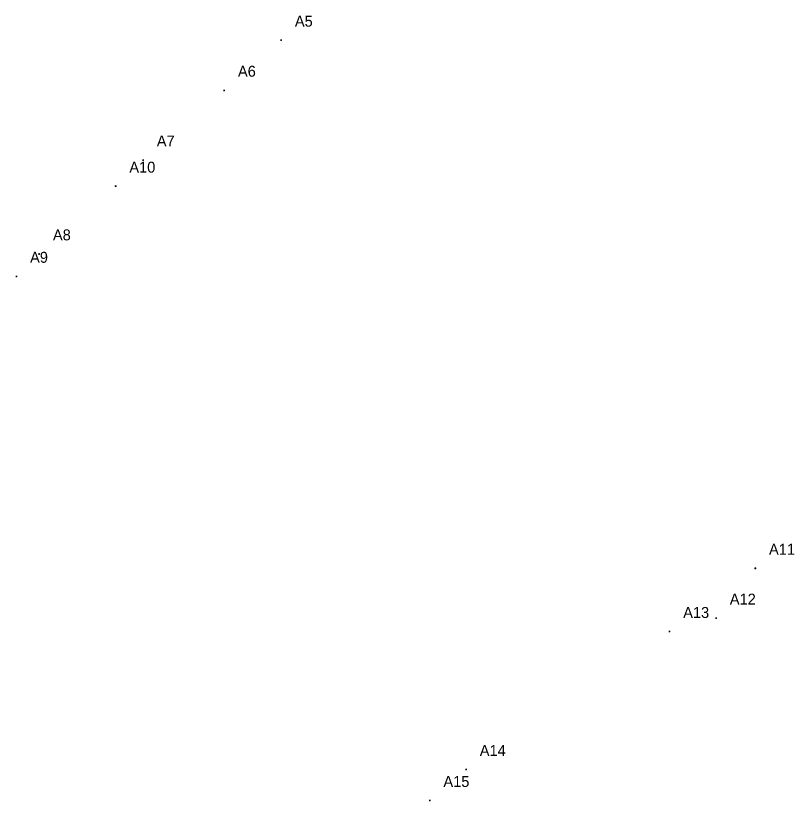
# Model space of a CAD drawing. Extents: x 1727960 to 1749562, y 651707 to 653731.
# Drawn here: x 1731235.4 to 1731520.4, y 651707.4 to 651995.2 of the extents above; entities that cross this region are included whole.
import ezdxf

# ---------------------------------------------------------------- set-up
doc = ezdxf.new("R2010")
doc.units = 0
doc.layers.add('SURVEY - DRAINAGE - Storm Sewer - Points - Locators', color=7, linetype='Continuous')
doc.layers.add('SURVEY - DRAINAGE - Storm Sewer - Points - Numbers', color=7, linetype='Continuous')

msp = doc.modelspace()

# ---------------------------------------------------------------- linework, layer by layer
at = {"layer": 'SURVEY - DRAINAGE - Storm Sewer - Points - Locators'}
for p, q in [((1731332.82, 651986.16), (1731332.32, 651986.16)), ((1731332.57, 651985.91), (1731332.57, 651986.41)), ((1731332.57, 651986.16), (1731332.57, 651986.16)), ((1731332.57, 651986.16), (1731332.57, 651986.16)), ((1731311.98, 651967.82), (1731311.48, 651967.82)), ((1731311.73, 651967.57), (1731311.73, 651968.07)), ((1731311.73, 651967.82), (1731311.73, 651967.82)), ((1731311.73, 651967.82), (1731311.73, 651967.82)), ((1731282.27, 651942.28), (1731281.77, 651942.28)), ((1731282.02, 651942.03), (1731282.02, 651942.53)), ((1731282.02, 651942.28), (1731282.02, 651942.28)), ((1731282.02, 651942.28), (1731282.02, 651942.28)), ((1731271.96, 651932.43), (1731271.96, 651932.93)), ((1731272.21, 651932.68), (1731271.71, 651932.68)), ((1731271.96, 651932.68), (1731271.96, 651932.68)), ((1731271.96, 651932.68), (1731271.96, 651932.68)), ((1731244.24, 651907.88), (1731243.74, 651907.88)), ((1731243.99, 651907.63), (1731243.99, 651908.13)), ((1731243.99, 651907.88), (1731243.99, 651907.88)), ((1731243.99, 651907.88), (1731243.99, 651907.88)), ((1731235.86, 651899.68), (1731235.36, 651899.68)), ((1731235.61, 651899.43), (1731235.61, 651899.93)), ((1731235.61, 651899.68), (1731235.61, 651899.68)), ((1731235.61, 651899.68), (1731235.61, 651899.68)), ((1731506.42, 651792.75), (1731505.92, 651792.75)), ((1731506.17, 651792.5), (1731506.17, 651793)), ((1731506.17, 651792.75), (1731506.17, 651792.75)), ((1731506.17, 651792.75), (1731506.17, 651792.75)), ((1731491.82, 651774.23), (1731491.82, 651774.73)), ((1731492.07, 651774.48), (1731491.57, 651774.48)), ((1731491.82, 651774.48), (1731491.82, 651774.48)), ((1731491.82, 651774.48), (1731491.82, 651774.48)), ((1731475, 651769.58), (1731474.5, 651769.58)), ((1731474.75, 651769.33), (1731474.75, 651769.83)), ((1731474.75, 651769.58), (1731474.75, 651769.58)), ((1731474.75, 651769.58), (1731474.75, 651769.58)), ((1731400.52, 651719.02), (1731400.02, 651719.02)), ((1731400.27, 651718.77), (1731400.27, 651719.27)), ((1731400.27, 651719.02), (1731400.27, 651719.02)), ((1731400.27, 651719.02), (1731400.27, 651719.02)), ((1731387.21, 651707.68), (1731386.71, 651707.68)), ((1731386.96, 651707.43), (1731386.96, 651707.93)), ((1731386.96, 651707.68), (1731386.96, 651707.68)), ((1731386.96, 651707.68), (1731386.96, 651707.68))]:
    msp.add_line(p, q, dxfattribs=at)

# ---------------------------------------------------------------- texts
at = {"layer": 'SURVEY - DRAINAGE - Storm Sewer - Points - Numbers'}
for s, p in [('A5', (1731337.57, 651991.16)), ('A6', (1731316.73, 651972.82)), ('A7', (1731287.02, 651947.28)), ('A10', (1731276.96, 651937.68)), ('A8', (1731248.99, 651912.88)), ('A9', (1731240.61, 651904.68)), ('A11', (1731511.17, 651797.75)), ('A12', (1731496.82, 651779.48)), ('A13', (1731479.75, 651774.58)), ('A14', (1731405.27, 651724.02)), ('A15', (1731391.96, 651712.68))]:
    msp.add_text(s, height=4, dxfattribs=at).set_placement(p)

doc.saveas('drawing.dxf')
